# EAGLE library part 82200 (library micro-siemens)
MICROPROCESSOR/PERIPHERAL DEVICE
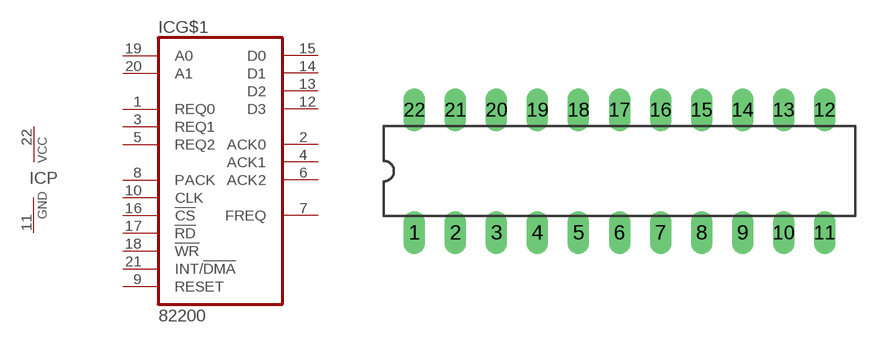
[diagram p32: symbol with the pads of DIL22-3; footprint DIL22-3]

Designator prefix IC; gates G$1=82200 P=VCCGND

## 82200 (OC_FARNELL: unknown; OC_NEWARK: unknown)  [DIL22-3]
1  G$1:REQ0  in
2  G$1:ACK0  out
3  G$1:REQ1  in
4  G$1:ACK1  out
5  G$1:REQ2  in
6  G$1:ACK2  out
7  G$1:FREQ  out
8  G$1:PACK  in
9  G$1:RESET  in
10  G$1:CLK  in
11  P:GND  pwr
12  G$1:D3
13  G$1:D2
14  G$1:D1
15  G$1:D0
16  G$1:!CS  in
17  G$1:!RD  in
18  G$1:!WR  in
19  G$1:A0  in
20  G$1:A1  in
21  G$1:INT/!DMA  in
22  P:VCC  pwr

## Footprint DIL22-3 (pad centres in mm)
Dual In Line Package 0.3 inch
drill 0.813 long: 1 -12.7,-3.81; 2 -10.16,-3.81; 3 -7.62,-3.81; 4 -5.08,-3.81; 5 -2.54,-3.81; 6 0,-3.81; 7 2.54,-3.81; 8 5.08,-3.81; 9 7.62,-3.81; 10 10.16,-3.81; 11 12.7,-3.81; 12 12.7,3.81; 13 10.16,3.81; 14 7.62,3.81; 15 5.08,3.81; 16 2.54,3.81; 17 0,3.81; 18 -2.54,3.81; 19 -5.08,3.81; 20 -7.62,3.81; 21 -10.16,3.81; 22 -12.7,3.81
